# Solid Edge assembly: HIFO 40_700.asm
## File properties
Title: Zylinder
Author: ahadarics
Template: iso assembly.asm
Last saved by: ahadarics
Revision: 56
Application: Solid Edge
Username: ahadarics
Dokumentum tartalom típus: 1
Document Number: HIFO 40/700
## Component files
Profilrohr 40_700.par
Mutter.par
Kolbenstange 40_700.par
Kit_1.par
Kit_2.par
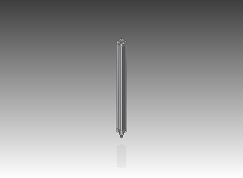
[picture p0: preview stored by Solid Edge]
